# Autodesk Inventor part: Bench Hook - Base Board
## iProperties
Created: 2010-02
Part Number: Bench Hook - Base Board
Document SubType Name: Modeling
Designer: Munford
Density: 1 g/cm^3
Author: Munford
Length: 200.000 mm
Width: 250.000 mm
Thickness: 12.000 mm
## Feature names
1. Extrusion1
